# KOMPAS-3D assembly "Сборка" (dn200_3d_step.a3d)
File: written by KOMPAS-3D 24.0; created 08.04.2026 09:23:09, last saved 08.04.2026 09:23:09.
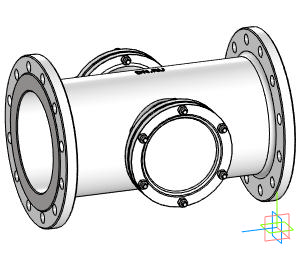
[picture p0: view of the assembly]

Document properties: Автор: Main; Полное имя файла: D:\DN.ru Аутсерс\Стекло смотровое DN.ru\Исходники\Стекло смотровое DN.ru SG2-34G-F тип В ГОСТ 21836-2021 Ду200 Ру16, углеродистая сталь, фланцевое\dn200_3d_step.a3d

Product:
- Component [detail]: Деталь  | qty 1  | Автор: Main; source file: ДетальДеталь.m3d
- Component [detail]: Стекло  | qty 2  | Автор: Main; source file: СтеклоСтекло.m3d
- Component [detail]: ANSI B18.2.4.2M - M10x1,5 - 16  | designation ANSI B18.2.4.2M - M10x1,5  | qty 1  | Автор: Main; source file: ANSI B18.2.4.2M - M10x1,5ANSI B18.2.4.2M - M10x1,5 - 16.m3d
- Component [detail]: ANSI B18.2.4.2M - M10x1,5 - 16  | designation ANSI B18.2.4.2M - M10x1,5  | qty 23  | Комментарий: Типы метрических   шестигранных гаек   2; Автор: Main; additional columns: Сталь, мягкая; source file: ANSI B18.2.4.2M - M10x1,5ANSI B18.2.4.2M - M10x1,5 - 16.m3d
- Part/product: Сборка

Referenced files in D:\DN.ru Аутсерс\Стекло смотровое DN.ru\Исходники\Стекло смотровое DN.ru SG2-34G-F тип В ГОСТ 21836-2021 Ду200 Ру16, углеродистая сталь, фланцевое\: ДетальДеталь.m3d, СтеклоСтекло.m3d, ANSI B18.2.4.2M - M10x1,5ANSI B18.2.4.2M - M10x1,5 - 16.m3d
